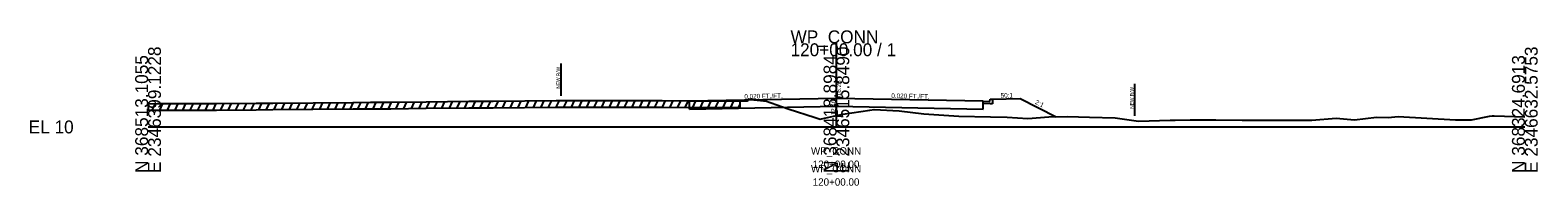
# Model space of a CAD drawing. Extents: x -26 to 2345577, y -10 to 367097.
# Drawn here: x 974.3 to 1302.8, y 7487.2 to 7521 of the extents above; entities that cross this region are included whole.
import ezdxf

# ---------------------------------------------------------------- set-up
doc = ezdxf.new("R2010")
doc.units = 0
for name, color, linetype in [('RD_GPK_XS_Cell', 7, 'Continuous'), ('RD_XS_Base', 7, 'Continuous'), ('RD_XS_CurbTop', 7, 'Continuous'), ('RD_XS_EarthShd', 7, 'Continuous'), ('RD_XS_ExGround', 7, 'Continuous'), ('RD_XS_ExPaveRet', 7, 'Continuous'), ('RD_XS_NewRW', 7, 'Continuous'), ('RD_XS_Pave', 7, 'Continuous'), ('RD_XS_TieSlope', 7, 'Continuous'), ('RD_XS_TX_Elev_EX', 7, 'Continuous'), ('RD_XS_TX_Elev_PR', 7, 'Continuous'), ('RD_XS_TX_Slope', 7, 'Continuous'), ('RD_XS_TX_Station', 7, 'Continuous'), ('RD_XS_TX_TOC', 7, 'Continuous')]:
    doc.layers.add(name, color=color, linetype=linetype)

msp = doc.modelspace()

# ---------------------------------------------------------------- linework, layer by layer
at = {"layer": 'RD_GPK_XS_Cell'}
for p, q in [((1150, 7500), (1150, 7518.18)), ((1000, 7500), (1150, 7500)), ((1150, 7500), (1300, 7500))]:
    msp.add_line(p, q, dxfattribs=at)
at = {"layer": 'RD_XS_Base'}
for p, q in [((1118, 7503.84), (1118, 7505.64)), ((1118, 7503.84), (1150, 7504.48)), ((1150, 7504.48), (1182, 7503.84)), ((1182, 7505.12), (1182, 7505.62)), ((1183.5, 7505.04), (1182, 7505.12)), ((1182, 7503.84), (1182, 7505.12)), ((1184, 7505.04), (1183.5, 7505.04)), ((1184, 7506.04), (1184, 7505.04))]:
    msp.add_line(p, q, dxfattribs=at)
at = {"layer": 'RD_XS_CurbTop'}
for p, q in [((1182, 7505.64), (1182, 7505.62)), ((1182, 7505.62), (1183.42, 7505.54)), ((1183.42, 7505.54), (1183.5, 7506.04)), ((1183.5, 7506.04), (1184, 7506.04))]:
    msp.add_line(p, q, dxfattribs=at)
at = {"layer": 'RD_XS_EarthShd'}
msp.add_line((1184, 7506.04), (1190, 7506.16), dxfattribs=at)
at = {"layer": 'RD_XS_ExGround'}
msp.add_lwpolyline([(1000, 7505.05), (1001.99, 7505.07), (1014.89, 7505.11), (1023.59, 7505.17), (1027.22, 7505.2), (1044.69, 7505.34), (1048.49, 7505.37), (1050.19, 7505.38), (1052.87, 7505.4), (1060.62, 7505.49), (1069.9, 7505.58), (1072.81, 7505.6), (1075.23, 7505.62), (1088.95, 7505.74), (1090.7, 7505.76), (1112.04, 7505.72), (1118.06, 7505.7), (1128.92, 7505.65), (1129.79, 7505.65), (1130.65, 7505.66), (1130.85, 7506.06), (1131.32, 7506.06), (1131.72, 7506.06), (1132.06, 7505.86), (1134.14, 7505.7), (1134.53, 7505.65), (1139.46, 7503.93), (1145.4, 7502.04), (1146.02, 7501.84), (1146.43, 7501.71), (1146.77, 7501.79), (1150, 7502.46), (1151.39, 7502.75), (1157.27, 7503.65), (1158.23, 7503.79), (1163.7, 7503.53), (1169.03, 7502.88), (1176.68, 7502.34), (1183.54, 7502.22), (1187.2, 7502.14), (1191.69, 7501.86), (1196.25, 7502.2), (1200.34, 7502.27), (1205.14, 7502.12), (1210.71, 7501.98), (1215.84, 7501.26), (1222.72, 7501.45), (1223.8, 7501.5), (1227.11, 7501.52), (1232.66, 7501.54), (1238.4, 7501.44), (1243.93, 7501.44), (1250.09, 7501.5), (1251.54, 7501.5), (1253.62, 7501.5), (1258.89, 7501.89), (1262.88, 7501.57), (1267.67, 7502.14), (1270.25, 7502.05), (1272.43, 7502.26), (1284.87, 7501.55), (1288.36, 7501.56), (1292.32, 7502.35), (1292.94, 7502.44), (1293.34, 7502.41), (1300, 7502.2)], dxfattribs=at)
at = {"layer": 'RD_XS_ExPaveRet'}
for p, q in [((1000, 7505.05), (1000, 7503.62)), ((1000.92, 7503.63), (1001.59, 7505.07)), ((1002.58, 7503.64), (1003.25, 7505.07)), ((1004.24, 7503.64), (1004.91, 7505.08)), ((1005.9, 7503.65), (1006.56, 7505.08)), ((1007.55, 7503.65), (1008.22, 7505.09)), ((1009.21, 7503.66), (1009.88, 7505.1)), ((1010.87, 7503.67), (1011.54, 7505.1)), ((1012.53, 7503.67), (1013.2, 7505.11)), ((1014.18, 7503.68), (1014.85, 7505.11)), ((1015.84, 7503.69), (1016.51, 7505.12)), ((1017.5, 7503.7), (1018.17, 7505.14)), ((1019.16, 7503.71), (1019.83, 7505.15)), ((1020.82, 7503.72), (1021.5, 7505.16)), ((1022.49, 7503.73), (1023.16, 7505.17)), ((1024.15, 7503.75), (1024.82, 7505.18)), ((1025.81, 7503.76), (1026.48, 7505.2)), ((1027.47, 7503.77), (1028.14, 7505.21)), ((1029.13, 7503.78), (1029.8, 7505.22)), ((1030.79, 7503.8), (1031.46, 7505.24)), ((1032.45, 7503.81), (1033.12, 7505.25)), ((1034.11, 7503.83), (1034.78, 7505.26)), ((1035.77, 7503.84), (1036.45, 7505.28)), ((1037.44, 7503.85), (1038.11, 7505.29)), ((1039.1, 7503.87), (1039.77, 7505.3)), ((1040.76, 7503.88), (1041.43, 7505.32)), ((1042.42, 7503.89), (1043.09, 7505.33)), ((1044.08, 7503.91), (1044.75, 7505.35)), ((1045.74, 7503.92), (1046.41, 7505.36)), ((1047.4, 7503.93), (1048.07, 7505.37)), ((1049.06, 7503.94), (1049.73, 7505.38)), ((1050.72, 7503.95), (1051.39, 7505.39)), ((1052.38, 7503.96), (1053.05, 7505.4)), ((1054.05, 7503.98), (1054.72, 7505.42)), ((1055.71, 7504), (1056.38, 7505.44)), ((1057.38, 7504.02), (1058.05, 7505.46)), ((1059.04, 7504.04), (1059.71, 7505.48)), ((1060.7, 7504.06), (1061.38, 7505.5)), ((1062.37, 7504.08), (1063.04, 7505.52)), ((1064.03, 7504.09), (1064.7, 7505.53)), ((1065.69, 7504.11), (1066.36, 7505.55)), ((1067.35, 7504.12), (1068.03, 7505.56)), ((1069.02, 7504.14), (1069.69, 7505.58)), ((1070.68, 7504.15), (1071.35, 7505.59)), ((1072.34, 7504.16), (1073.01, 7505.6)), ((1074, 7504.18), (1074.67, 7505.61)), ((1075.66, 7504.19), (1076.33, 7505.63)), ((1077.32, 7504.2), (1077.99, 7505.64)), ((1078.98, 7504.22), (1079.65, 7505.66)), ((1080.65, 7504.23), (1081.32, 7505.67)), ((1082.31, 7504.25), (1082.98, 7505.69)), ((1083.97, 7504.26), (1084.64, 7505.7)), ((1085.63, 7504.28), (1086.3, 7505.72)), ((1087.29, 7504.29), (1087.97, 7505.73)), ((1088.96, 7504.31), (1089.63, 7505.75)), ((1090.62, 7504.33), (1091.29, 7505.76)), ((1092.27, 7504.33), (1092.94, 7505.76)), ((1093.93, 7504.32), (1094.6, 7505.75)), ((1095.58, 7504.32), (1096.25, 7505.75)), ((1097.23, 7504.32), (1097.9, 7505.75)), ((1098.89, 7504.31), (1099.56, 7505.74)), ((1100.54, 7504.31), (1101.21, 7505.74)), ((1102.19, 7504.3), (1102.86, 7505.74)), ((1103.85, 7504.3), (1104.52, 7505.73)), ((1105.5, 7504.3), (1106.17, 7505.73)), ((1107.15, 7504.29), (1107.82, 7505.73)), ((1108.81, 7504.29), (1109.48, 7505.72)), ((1110.46, 7504.29), (1111.13, 7505.72)), ((1112.12, 7504.28), (1112.78, 7505.71)), ((1113.77, 7504.28), (1114.44, 7505.71)), ((1115.42, 7504.27), (1116.09, 7505.7)), ((1117.07, 7504.27), (1117.74, 7505.7)), ((1118.73, 7504.26), (1119.39, 7505.69)), ((1120.38, 7504.25), (1121.04, 7505.69)), ((1122.03, 7504.25), (1122.7, 7505.68)), ((1123.68, 7504.24), (1124.35, 7505.67)), ((1125.33, 7504.23), (1126, 7505.66)), ((1126.98, 7504.22), (1127.65, 7505.66)), ((1128.64, 7504.22), (1128.92, 7504.83)), ((1128.92, 7505.65), (1128.92, 7504.22))]:
    msp.add_line(p, q, dxfattribs=at)
msp.add_lwpolyline([(1000, 7503.62), (1002, 7503.64), (1014.89, 7503.68), (1023.59, 7503.74), (1027.22, 7503.77), (1044.69, 7503.91), (1048.5, 7503.94), (1050.19, 7503.95), (1052.87, 7503.96), (1060.62, 7504.06), (1069.9, 7504.15), (1072.81, 7504.17), (1075.23, 7504.18), (1088.96, 7504.31), (1090.7, 7504.33), (1112.04, 7504.28), (1118.06, 7504.26), (1128.92, 7504.22)], dxfattribs=at)
at = {"layer": 'RD_XS_NewRW'}
for p, q in [((1090, 7506.76), (1090, 7513.76)), ((1215, 7502.38), (1215, 7509.38))]:
    msp.add_line(p, q, dxfattribs=at)
at = {"layer": 'RD_XS_Pave'}
for p, q in [((1118, 7505.64), (1150, 7506.28)), ((1150, 7506.28), (1182, 7505.64))]:
    msp.add_line(p, q, dxfattribs=at)
at = {"layer": 'RD_XS_TieSlope'}
msp.add_line((1190, 7506.16), (1197.87, 7502.23), dxfattribs=at)

# ---------------------------------------------------------------- texts
at = {"layer": 'RD_GPK_XS_Cell'}
for s, p in [('WP_CONN', (1140, 7518.18)), ('120+00.00 / 1', (1140, 7515.38)), ('EL 10', (974, 7498.6))]:
    msp.add_text(s, height=2.8, dxfattribs=at).set_placement(p)
for s, p in [('E 2346399.1228', (1002.8, 7490)), ('E 2346515.8490', (1152.8, 7490)), ('E 2346632.5753', (1302.8, 7490)), ('N 368513.1055', (1000, 7490)), ('N 368418.8984', (1150, 7490)), ('N 368324.6913', (1300, 7490))]:
    msp.add_text(s, height=2.8, rotation=90, dxfattribs=at).set_placement(p)
at = {"layer": 'RD_XS_NewRW'}
for p in [(1089.75, 7508.34), (1214.75, 7503.97)]:
    msp.add_text('NEW R/W ', height=0.75, rotation=90, dxfattribs=at).set_placement(p)
at = {"layer": 'RD_XS_TX_Elev_EX'}
msp.add_text('12.46', height=1, rotation=90, dxfattribs=at).set_placement((1149.82, 7502.5))
at = {"layer": 'RD_XS_TX_Elev_PR'}
for s, rotation, p in [(' 16.28', 90, (1151, 7506.28)), ('50:1', 1.1458, (1185.79, 7506.35)), ('2:1', 333.4349, (1193.2, 7505.05))]:
    msp.add_text(s, height=1, rotation=rotation, dxfattribs=at).set_placement(p)
at = {"layer": 'RD_XS_TX_Slope'}
for rotation, p in [(1.1458, (1129.94, 7506.13)), (358.8542, (1161.95, 7506.29))]:
    msp.add_text('0.020 FT./FT.', height=1, rotation=rotation, dxfattribs=at).set_placement(p)
at = {"layer": 'RD_XS_TX_Station'}
for s, p in [('WP_CONN', (1144.45, 7493.99)), ('WP_CONN', (1144.45, 7490.13)), ('120+00.00', (1144.83, 7491.09)), ('120+00.00', (1144.83, 7487.23))]:
    msp.add_text(s, height=1.6, dxfattribs=at).set_placement(p)
at = {"layer": 'RD_XS_TX_TOC'}
msp.add_text('TOCRT', height=0.05, dxfattribs=at).set_placement((1183.22, 7505.99))

doc.saveas('drawing.dxf')
